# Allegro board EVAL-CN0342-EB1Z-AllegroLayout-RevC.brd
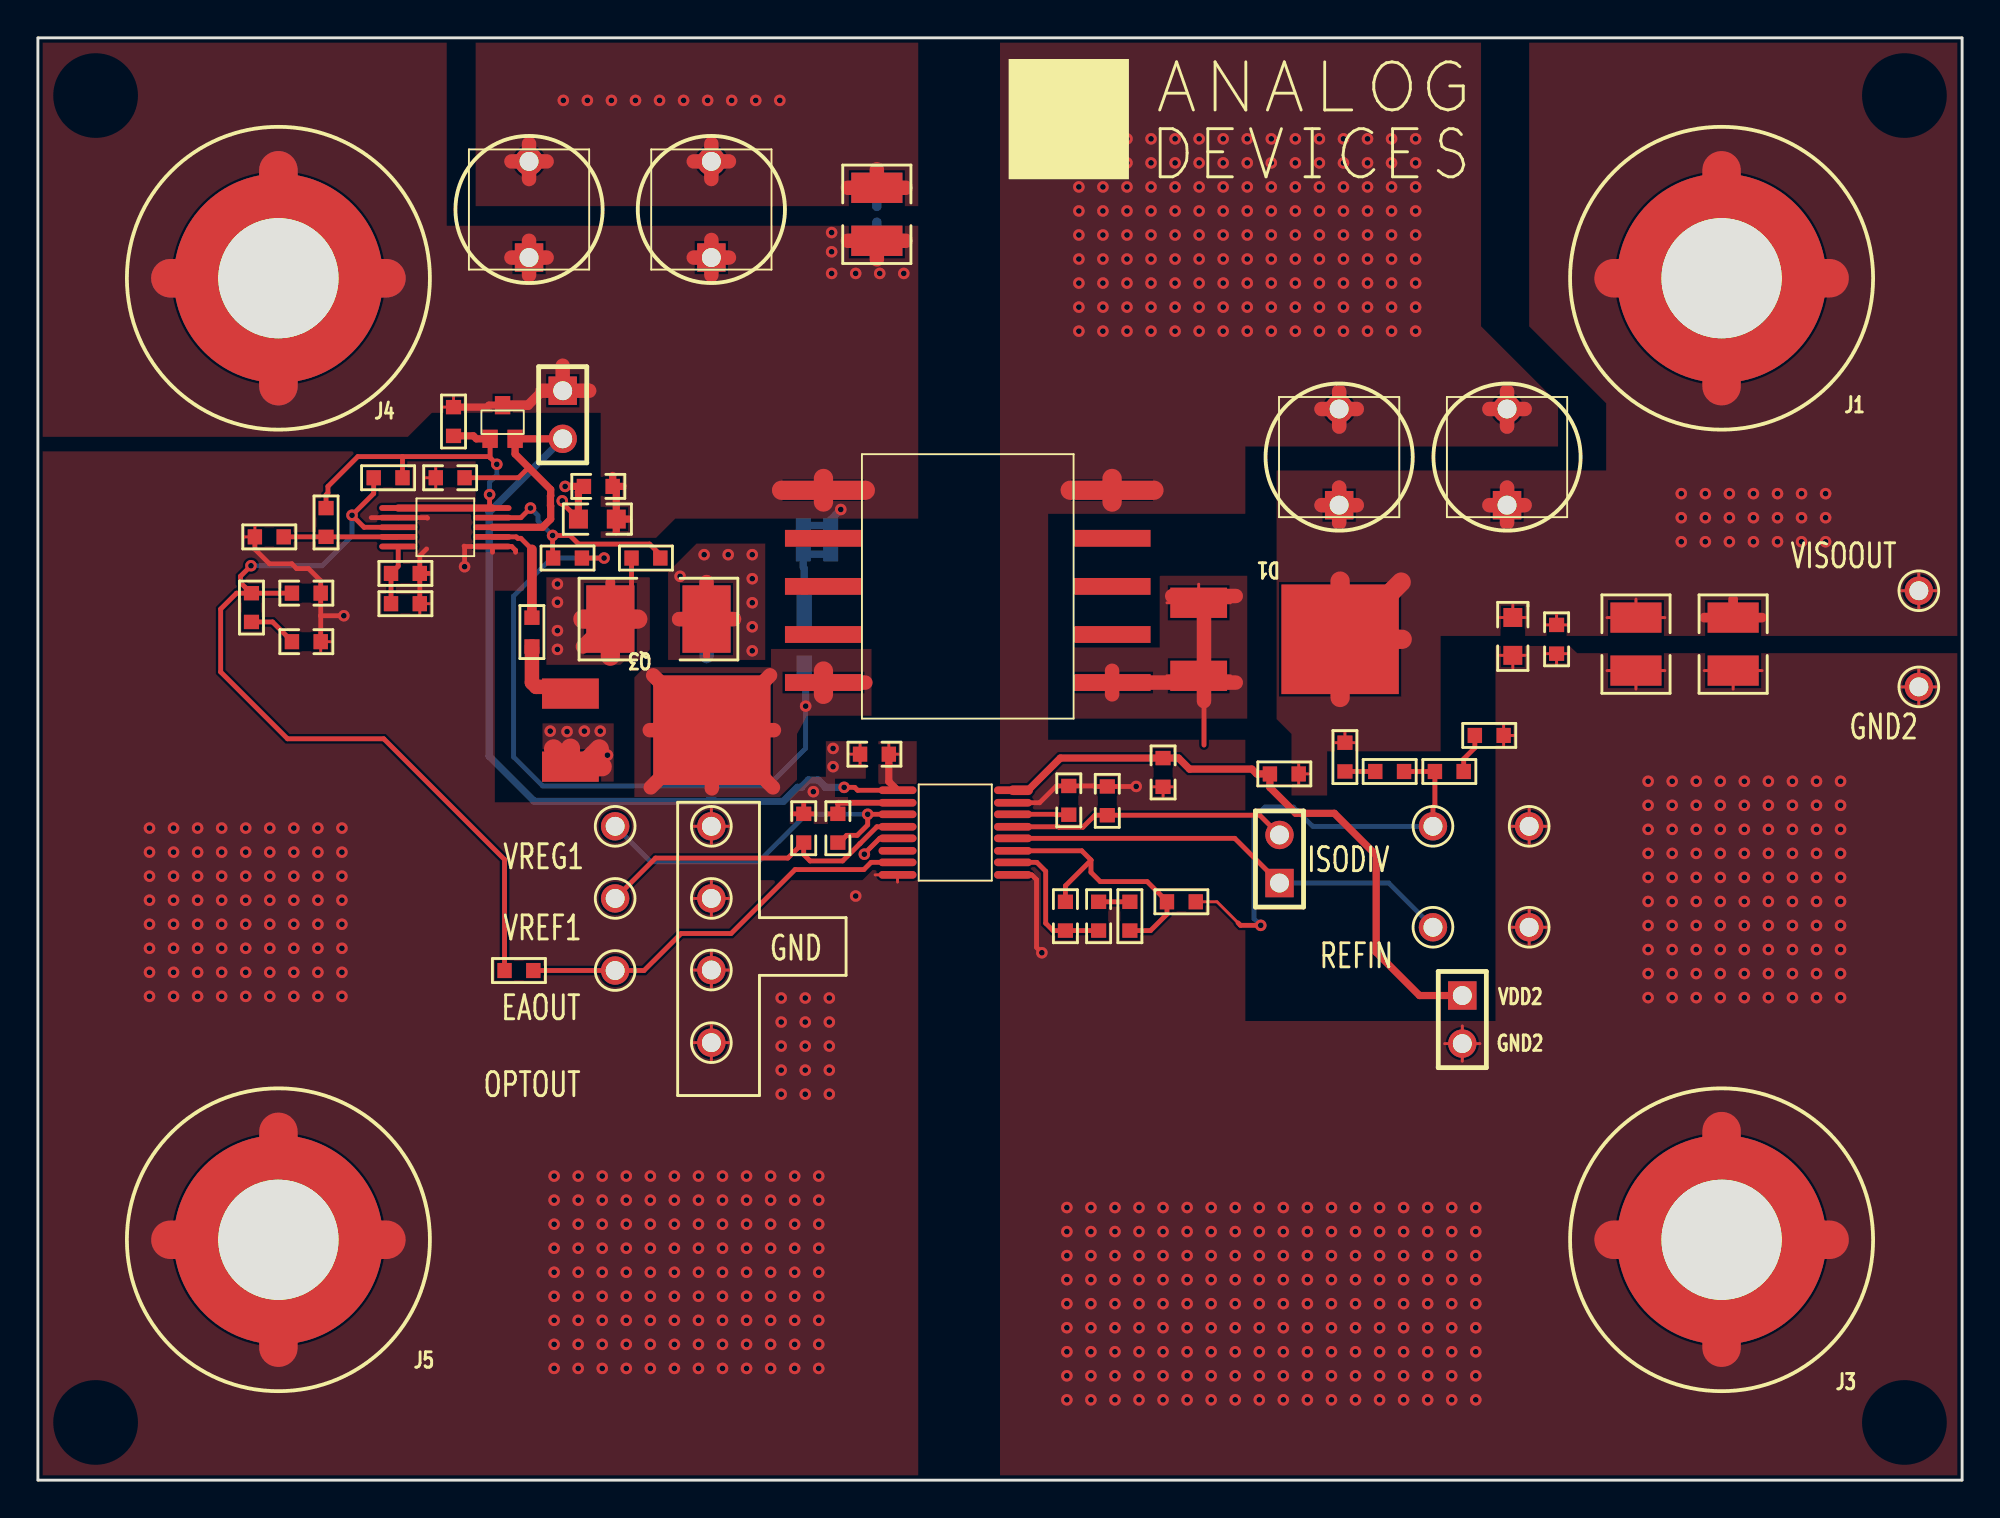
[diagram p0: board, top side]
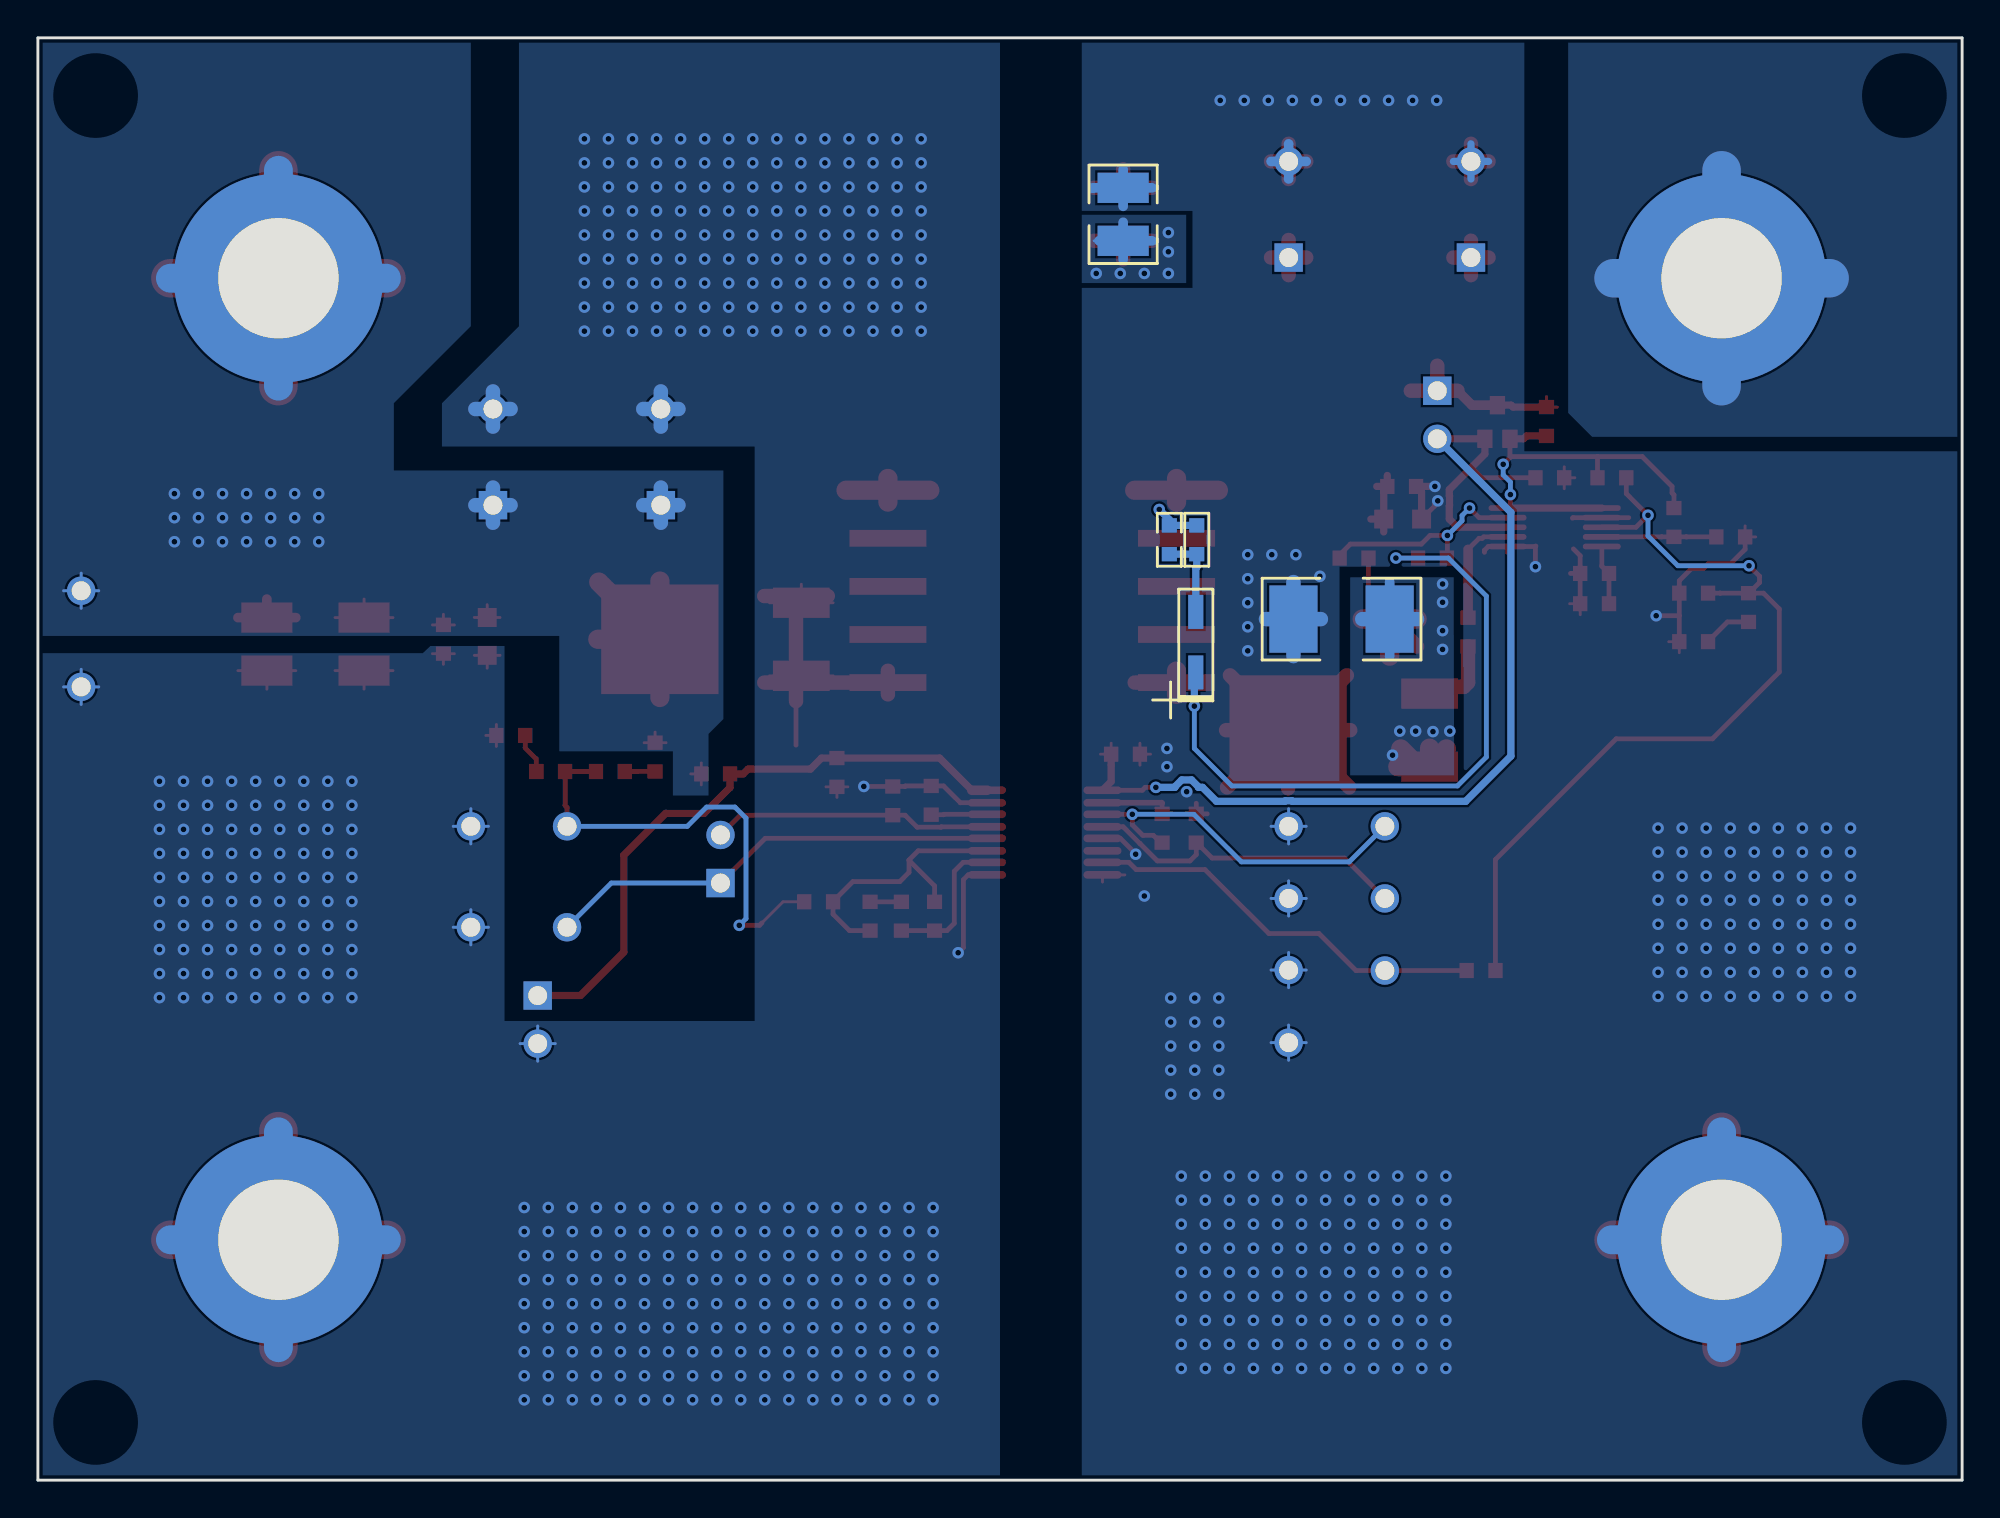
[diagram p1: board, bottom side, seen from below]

Outline 101.6 x 76.2 mm; copper layers: TOP, BOTTOM. Coordinates in mm from the lower left corner of the outline.
Outline path: 0,76.2 0,0 ; 0,76.2 0,0 ; 0,76.2 101.6,76.2 ; 0,76.2 101.6,76.2 ; 0,0 101.6,0 ; 0,0 101.6,0 ; 101.6,0 101.6,76.2 ; 101.6,0 101.6,76.2

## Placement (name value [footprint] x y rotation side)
C1  1uF  [C0603]  80.19 44.42 270 top
C2  10uF  [C0805]  77.88 44.58 270 top
C3  150uF  [CAX5]  68.71 54.05 90 top
C4  150uF  [CAX5]  77.57 54.05 90 top
C5  100nF  [C0603]  54.43 35.92 90 top
C6  100nF  [C0603]  42.24 34.44 90 top
C7  DP  [C0603]  14.17 44.3 0 top
C8  DP  [C0603]  14.17 46.86 0 top
C9  DP  [C0603]  56.01 29.79 90 top
C10  DP  [C0603]  54.25 29.79 90 top
C12  1uF  [C0603]  29.59 52.5 180 top
C13  10uF  [C0805]  29.54 50.77 180 top
C14  150uF  [CAX5]  35.56 67.13 90 top
C15  150uF  [CAX5]  25.93 67.13 90 top
C16  100nF  [C0603]  56.46 35.89 90 top
C17  1uF  [C0603]  44.17 38.35 180 top
C18  1uF  [C0603]  21.77 52.96 180 top
C19  100nF  [C0603]  40.44 34.44 90 top
C20  100nF  [C0603]  59.41 37.39 270 top
C21  DP  [C0603]  41.86 49.68 90 bottom
C23  47uF  [C1210]  84.38 44.17 270 top
C24  47uF  [C1210]  89.51 44.17 270 top
C25  47uF  [C1210]  44.3 66.88 90 top
C26  47uF  [C1210]  44.3 66.88 90 bottom
D1  MBRD1045G  [DPAK]  68.76 44.42 180 top
D2  MBR0540T1-D  [SOD-123]  40.46 44.27 90 bottom
J1  BANANA_JACK  [POWERJACK]  88.9 63.5 0 top
J3  BANANA_JACK  [POWERJACK]  88.9 12.7 0 top
J4  BANANA_JACK  [POWERJACK]  12.7 63.5 0 top
J5  BANANA_JACK  [POWERJACK]  12.7 12.7 0 top
J7  CON2x1  [HEADER2-100]  27.71 57.56 270 top
J14  CON2x1  [HEADER2-100]  75.21 25.6 270 top
J15  CON2x1  [HEADER2-100]  65.56 31.55 90 top
NOREF  -  [unnamed]  3.05 73.15 0 top
NOREF#2  -  [unnamed]  98.55 3.05 0 top
NOREF#3  -  [unnamed]  98.55 73.15 0 top
NOREF#4  -  [unnamed]  3.05 3.05 0 top
NOREF#5  -  [#2]  51.26 68.73 180 bottom
Q2  MMBT5089L  [SC70]  23.88 55.02 90 top
Q3  NTD18N06L  [DPAK]  35.59 39.62 180 top
R1  2k  [R0603]  76.63 39.34 0 top
R2  47k  [R0603]  74.52 37.44 0 top
R3  51k  [R0603]  71.37 37.44 0 top
R4  100k  [R0603]  69.01 38.2 270 top
R5  80  [R0603]  27.97 48.72 0 top
R6  100k  [R0603]  19.41 47.9 0 top
R7  DP  [R0603]  19.41 46.3 0 top
R8  DP  [R0603]  11.28 46.1 270 top
R9  DP  [R0603]  57.66 29.79 270 top
R11  0  [R0603]  60.38 30.56 0 top
R12  820  [R0603]  21.95 55.93 90 top
R13  100  [R0603]  65.81 37.31 180 top
R16  0  [R0603]  26.09 44.81 270 top
R17  DP  [R0603]  15.21 50.6 270 top
R18  0  [R0603]  12.22 49.83 0 top
R19  DP  [R0603]  40.41 49.68 90 bottom
R20  0  [R2010]  32.77 45.49 0 top
R21  0  [R2010]  32.77 45.49 0 bottom
R22  DP  [R0603]  32.11 48.72 180 top
R23  0  [R0603]  25.4 26.92 0 top
R24  0  [R0603]  18.49 52.96 0 top
TP1  TP-S  [HEADER1]  30.48 34.54 0 top
TP2  TP-S  [HEADER1]  30.48 30.73 0 top
TP3  TP-S  [HEADER1]  30.48 26.92 0 top
TP4  TP-S  [HEADER1]  73.66 29.21 0 top
TP6  TP-S  [HEADER1]  73.66 34.54 0 top
TP7  TP-S  [HEADER1]  35.56 34.54 0 top
TP8  TP-S  [HEADER1]  35.56 30.73 0 top
TP9  TP-S  [HEADER1]  35.56 26.95 0 top
TP10  TP-S  [HEADER1]  78.74 34.54 0 top
TP11  TP-S  [HEADER1]  78.74 29.21 0 top
TP13  TP-S  [HEADER1]  35.56 23.11 0 top
TP14  TP-S  [HEADER1]  99.31 41.91 0 top
TP15  TP-S  [HEADER1]  99.31 46.99 0 top
U2  ADuM3190  [QSOP-16]  48.44 34.21 0 top
U3  Halo 1 to 1 Flyback 2k5V iso  [TGB01]  49.1 47.22 0 top
U4  ADP1621  [MSOP-10]  21.51 50.34 0 top

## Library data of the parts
C1 C7-C10 C12 C17 C18 C21 = Cap_1U_0603_25V_X7R
C2 C13 = Cap_10U_0805_16V_X5R
C3 C4 C14 C15 = Cap_150U_RL2_0_6V_Alu
C5 C6 C16 C19 C20 = Cap_100n_0603_25V_X7R
C23-C26 = Cap_47U_1210_10V_X7R
D1 = MBRD1045G
D2 = MBR0540T1-D
J1 J3-J5 = BANANA_JACK
J7 J14 J15 = CON2x1
Q2 = MMBT5089L
Q3 = NTD18N06L
R1-R9 R11-R13 R16-R19 R22-R24 = Res_1k_0603_1%
R20 R21 = Res_0R5_2010_1%
TP1-TP4 TP6-TP11 TP13-TP15 = TP-S
U2 = ADuM3190
U3 = Halo 1 to 1 Flyback 2k5V iso
U4 = ADP1621

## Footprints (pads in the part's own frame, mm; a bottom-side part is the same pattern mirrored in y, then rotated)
C0603
  rect 0.76x0.8 smd: 1(-0.76,0) 2(0.76,0)
C0805
  rect 1x1 smd: 1(-1,0) 2(1,0)
C1210
  rect 1.6x2.7 smd: 1(-1.4,0) 2(1.4,0)
CAX5
  rect 1.5x1.5 hole 1: 1(-2.54,0)
  round 1.5 hole 1: 2(2.54,0)
DPAK
  rect 2.997x1.6 smd: 1(7.468,-1.93) 3(7.468,1.93)
  rect 6.198x5.791 smd: 4(0,0)
HEADER1
  round 1.5 hole 1: 1(0,0)
HEADER2-100
  rect 1.5x1.5 hole 1: 1(0,0)
  round 1.5 hole 1: 2(2.54,0)
MSOP-10
  oval 2.007x0.305 smd: 1(-2.489,1.016) 2(-2.489,0.508) 3(-2.489,0) 4(-2.489,-0.508) 5(-2.489,-1.016) 6(2.489,-1.016) 7(2.489,-0.508) 8(2.489,0) 9(2.489,0.508) 10(2.489,1.016)
POWERJACK
  round 11.05 hole 6.35: 1(0,0)
QSOP-16
  oval 2.007x0.406 smd: 1(-3.048,2.235) 2(-3.048,1.575) 3(-3.048,0.965) 4(-3.048,0.305) 5(-3.048,-0.305) 6(-3.048,-0.965) 7(-3.048,-1.575) 8(-3.048,-2.235) 9(3.048,-2.235) 10(3.048,-1.575) 11(3.048,-0.965) 12(3.048,-0.305) 13(3.048,0.305) 14(3.048,0.965) 15(3.048,1.575) 16(3.048,2.235)
R0603
  rect 0.76x0.8 smd: 1(-0.76,0) 2(0.76,0)
R2010
  rect 2.54x3.556 smd: 1(-2.54,0) 2(2.54,0)
SC70
  rect 0.965x0.813 smd: 1(0,0) 2(0,-1.321) 3(1.778,-0.66)
SOD-123
  rect 1.8x0.8 smd: 1(-1.6,0) 2(1.6,0)
TGB01
  rect 4.064x0.889 smd: 1(-7.62,5.08) 2(-7.62,2.54) 3(-7.62,0) 4(-7.62,-2.54) 5(-7.62,-5.08) 6(7.62,-5.08) 7(7.62,-2.54) 8(7.62,0) 9(7.62,2.54) 10(7.62,5.08)
unnamed
  round 0 hole 4.064 unplated: (0,0)

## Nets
GND1: C6.2 C7.2 C8.2 C12.2 C13.2 C14.2 C15.2 C17.2 C18.2 C19.2 C25.2 C26.2 J5.1(POWER IN) R6.2 R7.2 R18.1 R20.2 R21.2 TP7.1(VIA) TP8.1(VIA) TP9.1(VIA) TP13.1(VIA) U2.2(GND1_1) U2.5(NC_1) U2.8(GND1_2) U4.2(GND) U4.6(PGND)
GND2: C1.2 C2.2 C3.2 C4.2 C5.2 C16.2 C20.2 C23.2 C24.2 J3.1(POWER IN) J14.2 R1.2 TP10.1(VIA) TP11.1(VIA) TP14.1(VIA) U2.9(GND2_2) U2.15(GND2_1) U3.10
VDD1: C17.1 C18.1 J7.2 Q2.2(E) U2.1(VDD1) U4.8(PIN)
VDD_1621: Q2.1(B) R12.1 R17.1 R24.2 U4.1(SDSN) U4.10(IN)
VIN: C12.1 C13.1 C14.1 C15.1 C21.2 C25.1 C26.1 J4.1(POWER IN) J7.1 Q2.3(C) R12.2 R19.2 U3.1
COMP: C8.1 R8.1 R23.1 R24.1 U4.3(COMP)
EAOUT: R23.2 TP3.1(VIA) U2.7(EAOUT)
EAOUT2: U2.6(NC_2)
FB: R17.2 R18.2 U4.4(FB)
ISO_DIV: R2.1 R3.2 R11.2 TP6.1(VIA)
ISO_FB: C10.2 R9.2 R11.1 U2.11(FB)
ISO_REFIN: J15.1 TP4.1(VIA) U2.12(REFIN)
ISO_REFOUT: C16.1 J15.2 U2.13(REFOUT)
ISO_VDD2: C20.1 J14.1 R13.2 U2.16(VDD2)
ISO_VOUT: C1.1 C2.1 C3.1 C4.1 C23.1 C24.1 D1.4 J1.1(POWER IN) R4.1 R13.1 TP15.1(VIA)
ISO_VOUT_1: D1.1 D1.3 U3.6
REFOUT1: C19.1 TP2.1(VIA) U2.4(REFOUT1)
VREG1: C6.1 TP1.1(VIA) U2.3(VREG1)
N01085: R16.1 U4.7(GATE)
N02537: D2.1(ANODE) Q3.4(D) R5.2 U3.5
N02557: R5.1 R22.1 U4.9(CS)
N02646: R6.1 R7.1 U4.5(FREQ)
N03158: C7.1 R8.2
N03612: C9.1 C10.1 U2.10(COMP)
N11488: C9.2 R9.1
N11838: C5.1 U2.14(VREG2)
N15603: Q3.1(G) R16.2
N23766: Q3.3(S) R20.1 R21.1 R22.2
N36415: C21.1 D2.2(CATHODE) R19.1
N37525: R3.1 R4.2
N37627: R1.1 R2.2

Pads without a net: U3 2 3 4 7 8 9

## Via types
v1: diameter 0.61, hole 0.305, TOP to BOTTOM, 659 vias

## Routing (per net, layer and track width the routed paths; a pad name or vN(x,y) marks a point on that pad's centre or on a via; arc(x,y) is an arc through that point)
GND1: length 153.8
  TOP w0.152: 44.21,31.98 U2.8 45.39,31.6 ; 43.41,37.78 C17.2 ; C17.2 43.41,38.93 ; C17.2 42.85,38.35 ; TP7.1 35.56,35.47 ; TP7.1 34.63,34.54 ; TP7.1 36.49,34.54 ; TP7.1 35.56,33.62 ; 20.45,52.96 C18.2 ; C18.2 21.01,53.54 ; C18.2 21.01,52.38 ; 15.49,44.3 C7.2 14.93,43.72 ; TP9.1 35.56,27.88 ; TP9.1 34.63,26.95 ; TP9.1 36.49,26.95 ; TP9.1 35.56,26.02 ; 34.63,23.11 TP13.1 ; TP13.1 35.56,22.19 ; TP13.1 35.56,24.04 ; TP13.1 36.49,23.11 ; TP8.1 35.56,31.66 ; TP8.1 34.63,30.73 ; TP8.1 36.49,30.73 ; TP8.1 35.56,29.81 ; 11.46,50.41 R18.1 10.9,49.83 ; 20.72,46.3 R7.2 20.17,45.73
  TOP w0.254: U4.6 22.53,49.33 ; U4.6 24,49.02 ; U4.6 25.02,49.33 25.22,49.12 25.22,49.02 ; 22.53,49.33 v1(22.53,48.26) ; 22.53,49.33 22.5,49.35 ; 14.93,45.67 C7.2 ; 14.93,45.67 v1(16.15,45.67) ; 14.93,45.67 C8.2 14.93,47.52 14.29,48.16 13.67,48.16 13.41,48.41 12.23,48.41 11.46,49.18 R18.1 ; v1(43.64,33.07) 43.64,33.1 44.45,33.91 U2.5 ; R6.2 20.17,48.84 20.52,49.2 ; R6.2 R7.2 ; R6.2 20.68,47.9 ; C19.2 41.02,35.2 ; C19.2 39.86,35.2 ; C19.2 40.44,35.76 ; C13.2 27.86,51.45 27.86,51.57 v1(27.69,51.74) ; 17.6,50.85 U4.2 20.55,50.85 20.57,50.83 ; 41.66,35.2 C6.2 42.24,35.76
  TOP w0.305: U2.2 42.27,35.79 42.24,35.76
  TOP w0.381: v1(27.84,52.5) C12.2 28.54,52.21 C13.2 ; R20.2 35.31,43.54
  TOP w0.762: C25.2 45.83,68.28 ; C25.2 42.77,68.28 ; C25.2 44.3,69.26 ; R20.2 33.86,45.49 ; R20.2 36.75,45.49 ; R20.2 35.31,47.45 ; C14.2 35.56,70.6 ; C14.2 34.63,69.67 ; C14.2 35.56,68.74 ; C14.2 36.49,69.67 ; C15.2 25.93,68.74 ; C15.2 25.01,69.67 ; C15.2 25.93,70.6 ; C15.2 26.86,69.67
  TOP w2.032: J5.1 12.7,7 ; J5.1 18.4,12.7 ; J5.1 12.7,18.4 ; J5.1 7,12.7
  BOTTOM w0.152: 35.56,26.02 TP9.1 ; TP9.1 36.49,26.95 ; TP9.1 34.63,26.95 ; TP9.1 35.56,27.88 ; TP13.1 35.56,24.04 ; TP13.1 36.49,23.11 ; TP13.1 35.56,22.19 ; TP13.1 34.63,23.11 ; TP7.1 35.56,35.47 ; TP7.1 34.63,34.54 ; TP7.1 36.49,34.54 ; TP7.1 35.56,33.62 ; 34.63,30.73 TP8.1 ; TP8.1 36.49,30.73 ; TP8.1 35.56,29.81 ; TP8.1 35.56,31.66
  BOTTOM w0.381: C15.2 26.86,69.67 ; C15.2 25.93,68.74 ; C15.2 25.01,69.67 ; C15.2 25.93,70.6
  BOTTOM w0.508: C14.2 34.63,69.67 ; C14.2 35.56,68.74 ; C14.2 36.49,69.67 ; C14.2 35.56,70.6 ; 45.9,68.25 45.87,68.28 C25.2 ; C25.2 44.3,69.26 ; C25.2 42.77,68.28 ; C25.2 44.3,67.3
  BOTTOM w0.762: 36.75,45.49 R20.2 ; R20.2 35.31,47.45 ; R20.2 33.86,45.49 ; R20.2 35.31,43.54
  BOTTOM w1.524: J5.1 12.7,18.4 ; J5.1 18.52,12.7 ; J5.1 12.7,7 ; J5.1 7,12.7
  vias: v1(5.89,34.45) v1(5.89,33.18) v1(5.89,31.91) v1(5.89,30.64) v1(5.89,29.37) v1(5.89,28.1) v1(5.89,26.83) v1(5.89,25.56) v1(7.16,34.45) v1(7.16,33.18) v1(7.16,31.91) v1(7.16,30.64) v1(7.16,29.37) v1(7.16,28.1) v1(7.16,26.83) v1(7.16,25.56) v1(8.43,34.45) v1(8.43,33.18) v1(8.43,31.91) v1(8.43,30.64) v1(8.43,29.37) v1(8.43,28.1) v1(8.43,26.83) v1(8.43,25.56) v1(9.7,34.45) v1(9.7,33.18) v1(9.7,31.91) v1(9.7,30.64) v1(9.7,29.37) v1(9.7,28.1) v1(9.7,26.83) v1(9.7,25.56) v1(10.97,34.45) v1(10.97,33.18) v1(10.97,31.91) v1(10.97,30.64) v1(10.97,29.37) v1(10.97,28.1) v1(10.97,26.83) v1(10.97,25.56) v1(12.24,34.45) v1(12.24,33.18) v1(12.24,31.91) v1(12.24,30.64) v1(12.24,29.37) v1(12.24,28.1) v1(12.24,26.83) v1(12.24,25.56) v1(13.51,34.45) v1(13.51,33.18) v1(13.51,31.91) v1(13.51,30.64) v1(13.51,29.37) v1(13.51,28.1) v1(13.51,26.83) v1(13.51,25.56) v1(14.78,34.45) v1(14.78,33.18) v1(14.78,31.91) v1(14.78,30.64) v1(14.78,29.37) v1(14.78,28.1) v1(14.78,26.83) v1(14.78,25.56) v1(16.05,34.45) v1(16.05,33.18) v1(16.05,31.91) v1(16.05,30.64) v1(16.05,29.37) v1(16.05,28.1) v1(16.05,26.83) v1(16.05,25.56) v1(27.26,16.06) v1(27.26,14.79) v1(27.26,13.52) v1(27.26,12.25) v1(27.26,10.98) v1(27.26,9.71) v1(27.26,8.44) v1(27.26,7.17) v1(27.26,5.9) v1(27.74,72.9) v1(28.53,16.06) v1(28.53,14.79) v1(28.53,13.52) v1(28.53,12.25) v1(28.53,10.98) v1(28.53,9.71) v1(28.53,8.44) v1(28.53,7.17) v1(28.53,5.9) v1(29.01,72.9) v1(29.8,16.06) v1(29.8,14.79) v1(29.8,13.52) v1(29.8,12.25) v1(29.8,10.98) v1(29.8,9.71) v1(29.8,8.44) v1(29.8,7.17) v1(29.8,5.9) v1(30.28,72.9) v1(31.07,16.06) v1(31.07,14.79) v1(31.07,13.52) v1(31.07,12.25) v1(31.07,10.98) v1(31.07,9.71) v1(31.07,8.44) v1(31.07,7.17) v1(31.07,5.9) v1(31.55,72.9) v1(32.34,16.06) v1(32.34,14.79) v1(32.34,13.52) v1(32.34,12.25) v1(32.34,10.98) v1(32.34,9.71) v1(32.34,8.44) v1(32.34,7.17) v1(32.34,5.9) v1(32.82,72.9) v1(33.61,16.06) v1(33.61,14.79) v1(33.61,13.52) v1(33.61,12.25) v1(33.61,10.98) v1(33.61,9.71) v1(33.61,8.44) v1(33.61,7.17) v1(33.61,5.9) v1(33.91,47.75) v1(34.09,72.9) v1(34.88,16.06) v1(34.88,14.79) v1(34.88,13.52) v1(34.88,12.25) v1(34.88,10.98) v1(34.88,9.71) v1(34.88,8.44) v1(34.88,7.17) v1(34.88,5.9) v1(35.18,48.9) v1(35.36,72.9) v1(36.15,16.06) v1(36.15,14.79) v1(36.15,13.52) v1(36.15,12.25) v1(36.15,10.98) v1(36.15,9.71) v1(36.15,8.44) v1(36.15,7.17) v1(36.15,5.9) v1(36.45,48.9) v1(36.63,72.9) v1(37.42,16.06) v1(37.42,14.79) v1(37.42,13.52) v1(37.42,12.25) v1(37.42,10.98) v1(37.42,9.71) v1(37.42,8.44) v1(37.42,7.17) v1(37.42,5.9) v1(37.72,48.9) v1(37.72,47.62) v1(37.72,46.36) v1(37.72,45.09) v1(37.72,43.81) v1(37.9,72.9) v1(38.69,16.06) v1(38.69,14.79) v1(38.69,13.52) v1(38.69,12.25) v1(38.69,10.98) v1(38.69,9.71) v1(38.69,8.44) v1(38.69,7.17) v1(38.69,5.9) v1(39.17,72.9) v1(39.25,25.47) v1(39.25,24.2) v1(39.25,22.93) v1(39.25,21.66) v1(39.25,20.39) v1(39.96,16.06) v1(39.96,14.79) v1(39.96,13.52) v1(39.96,12.25) v1(39.96,10.98) v1(39.96,9.71) v1(39.96,8.44) v1(39.96,7.17) v1(39.96,5.9) v1(40.52,25.47) v1(40.52,24.2) v1(40.52,22.93) v1(40.52,21.66) v1(40.52,20.39) v1(40.94,36.37) v1(41.23,16.06) v1(41.23,14.79) v1(41.23,13.52) v1(41.23,12.25) v1(41.23,10.98) v1(41.23,9.71) v1(41.23,8.44) v1(41.23,7.17) v1(41.23,5.9) v1(41.79,25.47) v1(41.79,24.2) v1(41.79,22.93) v1(41.79,21.66) v1(41.79,20.39) v1(41.99,38.66) v1(41.99,37.69) v1(43.18,30.86)
GND2: length 123.4
  TOP w0.152: 74.28,23.06 J14.2 ; J14.2 75.21,22.13 ; J14.2 75.21,23.99 ; J14.2 76.14,23.06 ; 87.98,42.77 C24.2 ; C24.2 91.04,42.77 ; C24.2 89.51,41.79 ; 99.31,40.98 TP14.1 ; TP14.1 100.24,41.91 ; TP14.1 99.31,42.84 ; TP14.1 98.39,41.91 ; 77.81,34.54 TP10.1 ; TP10.1 78.74,33.62 ; TP10.1 78.74,35.47 ; TP10.1 79.67,34.54 ; 77.2,43.58 C2.2 ; C2.2 78.55,43.58 ; C2.2 77.88,42.9 ; TP11.1 79.67,29.21 ; TP11.1 78.74,28.28 ; TP11.1 77.81,29.21 ; TP11.1 78.74,30.14 ; 58.83,36.63 C20.2 ; C20.2 59.41,36.07 ; C20.2 59.99,36.63 ; 79.61,43.66 C1.2 ; C1.2 80.77,43.66 ; C1.2 80.19,43.11 ; C23.2 85.91,42.77 ; C23.2 82.85,42.77 ; C23.2 84.38,41.79 ; R1.2 77.39,39.92 ; R1.2 77.39,38.77 ; R1.2 77.95,39.34
  TOP w0.254: v1(53.01,27.86) 52.73,28.14 52.73,31.72 52.48,31.98 U2.9 ; v1(57.99,36.65) C16.2 55.81,36.65 55.78,36.68 C5.2 53.78,36.68 52.89,35.79 U2.15
  TOP w0.762: C3.2 67.78,56.59 ; C3.2 69.64,56.59 ; C3.2 68.71,57.52 ; C3.2 68.71,55.66 ; C4.2 76.64,56.59 ; C4.2 77.57,57.52 ; C4.2 77.57,55.66 ; C4.2 78.5,56.59
  TOP w1.016: U3.10 58.93,52.3 ; U3.10 56.72,51.68 ; U3.10 54.51,52.3 ; U3.10 56.72,52.92
  TOP w2.032: J3.1 94.6,12.7 ; J3.1 88.9,7 ; J3.1 83.2,12.7 ; J3.1 88.9,18.44
  BOTTOM w0.152: 75.21,22.13 J14.2 ; J14.2 74.28,23.06 ; J14.2 75.21,23.99 ; J14.2 76.14,23.06 ; 77.81,29.21 TP11.1 ; TP11.1 78.74,30.14 ; TP11.1 79.67,29.21 ; TP11.1 78.74,28.28 ; TP10.1 79.67,34.54 ; TP10.1 77.81,34.54 ; TP10.1 78.74,33.62 ; TP10.1 78.74,35.47 ; TP14.1 100.24,41.91 ; TP14.1 99.31,42.84 ; TP14.1 99.31,40.98 ; TP14.1 98.39,41.91
  BOTTOM w0.762: C3.2 69.64,56.59 ; C3.2 67.78,56.59 ; C3.2 68.71,55.66 ; C3.2 68.71,57.52 ; C4.2 78.5,56.59 ; C4.2 76.64,56.59 ; C4.2 77.57,57.52 ; C4.2 77.57,55.66
  BOTTOM w1.524: J3.1 88.9,7 ; J3.1 88.9,18.4 ; J3.1 94.6,12.7 ; J3.1 83.2,12.7
  vias: v1(54.33,14.4) v1(54.33,13.13) v1(54.33,11.86) v1(54.33,10.59) v1(54.33,9.32) v1(54.33,8.05) v1(54.33,6.78) v1(54.33,5.51) v1(54.33,4.24) v1(54.96,70.86) v1(54.96,69.59) v1(54.96,68.32) v1(54.96,67.05) v1(54.96,65.78) v1(54.96,64.51) v1(54.96,63.24) v1(54.96,61.97) v1(54.96,60.7) v1(55.6,14.4) v1(55.6,13.13) v1(55.6,11.86) v1(55.6,10.59) v1(55.6,9.32) v1(55.6,8.05) v1(55.6,6.78) v1(55.6,5.51) v1(55.6,4.24) v1(56.23,70.86) v1(56.23,69.59) v1(56.23,68.32) v1(56.23,67.05) v1(56.23,65.78) v1(56.23,64.51) v1(56.23,63.24) v1(56.23,61.97) v1(56.23,60.7) v1(56.87,14.4) v1(56.87,13.13) v1(56.87,11.86) v1(56.87,10.59) v1(56.87,9.32) v1(56.87,8.05) v1(56.87,6.78) v1(56.87,5.51) v1(56.87,4.24) v1(57.5,70.86) v1(57.5,69.59) v1(57.5,68.32) v1(57.5,67.05) v1(57.5,65.78) v1(57.5,64.51) v1(57.5,63.24) v1(57.5,61.97) v1(57.5,60.7) v1(58.14,14.4) v1(58.14,13.13) v1(58.14,11.86) v1(58.14,10.59) v1(58.14,9.32) v1(58.14,8.05) v1(58.14,6.78) v1(58.14,5.51) v1(58.14,4.24) v1(58.77,70.86) v1(58.77,69.59) v1(58.77,68.32) v1(58.77,67.05) v1(58.77,65.78) v1(58.77,64.51) v1(58.77,63.24) v1(58.77,61.97) v1(58.77,60.7) v1(59.41,14.4) v1(59.41,13.13) v1(59.41,11.86) v1(59.41,10.59) v1(59.41,9.32) v1(59.41,8.05) v1(59.41,6.78) v1(59.41,5.51) v1(59.41,4.24) v1(60.04,70.86) v1(60.04,69.59) v1(60.04,68.32) v1(60.04,67.05) v1(60.04,65.78) v1(60.04,64.51) v1(60.04,63.24) v1(60.04,61.97) v1(60.04,60.7) v1(60.68,14.4) v1(60.68,13.13) v1(60.68,11.86) v1(60.68,10.59) v1(60.68,9.32) v1(60.68,8.05) v1(60.68,6.78) v1(60.68,5.51) v1(60.68,4.24) v1(61.31,70.86) v1(61.31,69.59) v1(61.31,68.32) v1(61.31,67.05) v1(61.31,65.78) v1(61.31,64.51) v1(61.31,63.24) v1(61.31,61.97) v1(61.31,60.7) v1(61.95,14.4) v1(61.95,13.13) v1(61.95,11.86) v1(61.95,10.59) v1(61.95,9.32) v1(61.95,8.05) v1(61.95,6.78) v1(61.95,5.51) v1(61.95,4.24) v1(62.58,70.86) v1(62.58,69.59) v1(62.58,68.32) v1(62.58,67.05) v1(62.58,65.78) v1(62.58,64.51) v1(62.58,63.24) v1(62.58,61.97) v1(62.58,60.7) v1(63.22,14.4) v1(63.22,13.13) v1(63.22,11.86) v1(63.22,10.59) v1(63.22,9.32) v1(63.22,8.05) v1(63.22,6.78) v1(63.22,5.51) v1(63.22,4.24) v1(63.85,70.86) v1(63.85,69.59) v1(63.85,68.32) v1(63.85,67.05) v1(63.85,65.78) v1(63.85,64.51) v1(63.85,63.24) v1(63.85,61.97) v1(63.85,60.7) v1(64.49,14.4) v1(64.49,13.13) v1(64.49,11.86) v1(64.49,10.59) v1(64.49,9.32) v1(64.49,8.05) v1(64.49,6.78) v1(64.49,5.51) v1(64.49,4.24) v1(65.12,70.86) v1(65.12,69.59) v1(65.12,68.32) v1(65.12,67.05) v1(65.12,65.78) v1(65.12,64.51) v1(65.12,63.24) v1(65.12,61.97) v1(65.12,60.7) v1(65.76,14.4) v1(65.76,13.13) v1(65.76,11.86) v1(65.76,10.59) v1(65.76,9.32) v1(65.76,8.05) v1(65.76,6.78) v1(65.76,5.51) v1(65.76,4.24) v1(66.39,70.86) v1(66.39,69.59) v1(66.39,68.32) v1(66.39,67.05) v1(66.39,65.78) v1(66.39,64.51) v1(66.39,63.24) v1(66.39,61.97) v1(66.39,60.7) v1(67.03,14.4) v1(67.03,13.13) v1(67.03,11.86) v1(67.03,10.59) v1(67.03,9.32) v1(67.03,8.05) v1(67.03,6.78) v1(67.03,5.51) v1(67.03,4.24) v1(67.66,70.86) v1(67.66,69.59) v1(67.66,68.32) v1(67.66,67.05) v1(67.66,65.78) v1(67.66,64.51) v1(67.66,63.24) v1(67.66,61.97) v1(67.66,60.7) v1(68.3,14.4) v1(68.3,13.13) v1(68.3,11.86) v1(68.3,10.59) v1(68.3,9.32) v1(68.3,8.05) v1(68.3,6.78) v1(68.3,5.51) v1(68.3,4.24) v1(68.93,70.86) v1(68.93,69.59) v1(68.93,68.32) v1(68.93,67.05) v1(68.93,65.78) v1(68.93,64.51) v1(68.93,63.24) v1(68.93,61.97) v1(68.93,60.7) v1(69.57,14.4) v1(69.57,13.13) v1(69.57,11.86) v1(69.57,10.59) v1(69.57,9.32) v1(69.57,8.05) v1(69.57,6.78) v1(69.57,5.51) v1(69.57,4.24) v1(70.2,70.86) v1(70.2,69.59) v1(70.2,68.32) v1(70.2,67.05) v1(70.2,65.78) v1(70.2,64.51) v1(70.2,63.24) v1(70.2,61.97) v1(70.2,60.7) v1(70.84,14.4) v1(70.84,13.13) v1(70.84,11.86) v1(70.84,10.59) v1(70.84,9.32) v1(70.84,8.05) v1(70.84,6.78) v1(70.84,5.51) v1(70.84,4.24) v1(71.47,70.86) v1(71.47,69.59) v1(71.47,68.32) v1(71.47,67.05) v1(71.47,65.78) v1(71.47,64.51) v1(71.47,63.24) v1(71.47,61.97) v1(71.47,60.7) v1(72.11,14.4) v1(72.11,13.13) v1(72.11,11.86) v1(72.11,10.59) v1(72.11,9.32) v1(72.11,8.05) v1(72.11,6.78) v1(72.11,5.51) v1(72.11,4.24) v1(72.74,70.86) v1(72.74,69.59) v1(72.74,68.32) v1(72.74,67.05) v1(72.74,65.78) v1(72.74,64.51) v1(72.74,63.24) v1(72.74,61.97) v1(72.74,60.7) v1(73.38,14.4) v1(73.38,13.13) v1(73.38,11.86) v1(73.38,10.59) v1(73.38,9.32) v1(73.38,8.05) v1(73.38,6.78) v1(73.38,5.51) v1(73.38,4.24) v1(74.65,14.4) v1(74.65,13.13) v1(74.65,11.86) v1(74.65,10.59) v1(74.65,9.32) v1(74.65,8.05) v1(74.65,6.78) v1(74.65,5.51) v1(74.65,4.24) v1(75.92,14.4) v1(75.92,13.13) v1(75.92,11.86) v1(75.92,10.59) v1(75.92,9.32) v1(75.92,8.05) v1(75.92,6.78) v1(75.92,5.51) v1(75.92,4.24) v1(85.02,36.92) v1(85.02,35.65) v1(85.02,34.38) v1(85.02,33.11) v1(85.02,31.84) v1(85.02,30.57) v1(85.02,29.3) v1(85.02,28.03) v1(85.02,26.76) v1(85.02,25.49) v1(86.29,36.92) v1(86.29,35.65) v1(86.29,34.38) v1(86.29,33.11) v1(86.29,31.84) v1(86.29,30.57) v1(86.29,29.3) v1(86.29,28.03) v1(86.29,26.76) v1(86.29,25.49) v1(87.56,36.92) v1(87.56,35.65) v1(87.56,34.38) v1(87.56,33.11) v1(87.56,31.84) v1(87.56,30.57) v1(87.56,29.3) v1(87.56,28.03) v1(87.56,26.76) v1(87.56,25.49) v1(88.83,36.92) v1(88.83,35.65) v1(88.83,34.38) v1(88.83,33.11) v1(88.83,31.84) v1(88.83,30.57) v1(88.83,29.3) v1(88.83,28.03) v1(88.83,26.76) v1(88.83,25.49) v1(90.1,36.92) v1(90.1,35.65) v1(90.1,34.38) v1(90.1,33.11) v1(90.1,31.84) v1(90.1,30.57) v1(90.1,29.3) v1(90.1,28.03) v1(90.1,26.76) v1(90.1,25.49) v1(91.37,36.92) v1(91.37,35.65) v1(91.37,34.38) v1(91.37,33.11) v1(91.37,31.84) v1(91.37,30.57) v1(91.37,29.3) v1(91.37,28.03) v1(91.37,26.76) v1(91.37,25.49) v1(92.64,36.92) v1(92.64,35.65) v1(92.64,34.38) v1(92.64,33.11) v1(92.64,31.84) v1(92.64,30.57) v1(92.64,29.3) v1(92.64,28.03) v1(92.64,26.76) v1(92.64,25.49) v1(93.91,36.92) v1(93.91,35.65) v1(93.91,34.38) v1(93.91,33.11) v1(93.91,31.84) v1(93.91,30.57) v1(93.91,29.3) v1(93.91,28.03) v1(93.91,26.76) v1(93.91,25.49) v1(95.18,36.92) v1(95.18,35.65) v1(95.18,34.38) v1(95.18,33.11) v1(95.18,31.84) v1(95.18,30.57) v1(95.18,29.3) v1(95.18,28.03) v1(95.18,26.76) v1(95.18,25.49)
VDD1: length 59.3
  TOP w0.152: 45.49,38.35 C17.1 44.93,38.93
  TOP w0.254: C18.1 25.37,52.96 25.91,53.5 ; v1(42.57,36.6) 43.13,36.6 43.28,36.45 U2.1
  TOP w0.381: C17.1 44.93,36.91 U2.1 ; J7.2 Q2.2 25.2,54.22 27.08,52.34 27.08,52.01 27.06,52 27.06,51.48 27.08,51.47 27.08,50.77 26.64,50.34 U4.8
  BOTTOM w0.381: J7.2 23.83,51.13 23.83,38.25 26.21,35.86 35.36,35.86 35.39,35.89 35.73,35.89 35.76,35.86 39.37,35.86 40.11,36.6 40.32,36.6 40.32,36.63 40.69,37 41.2,37 41.57,36.63 41.57,36.6 v1(42.57,36.6)
VDD_1621: length 22.5
  TOP w0.254: 19.25,54.08 16.89,54.08 15.32,52.5 15.32,52.16 15.21,52.06 R17.1 ; 19.25,54.08 19.25,54.07 R24.2 ; 19.25,54.08 23.83,54.08 23.88,54.03 ; 23.88,54.03 Q2.1 ; 23.88,54.03 v1(24.23,53.67) ; v1(23.85,52.07) 23.85,51.51 U4.10
  TOP w0.381: R12.1 23,55.17 23.15,55.02 Q2.1 ; U4.1 U4.10
  BOTTOM w0.254: v1(23.85,52.07) 23.85,52.73 24.23,53.11 v1(24.23,53.67)
VIN: length 84.5
  TOP w0.152: 21.37,56.69 R12.2 21.95,57.25
  TOP w0.381: C12.1 30.35,53.08 ; C12.1 30.54,52.31 C13.1 ; C12.1 30.91,52.5 ; R12.2 23.71,56.69 23.81,56.79 Q2.3 ; C13.1 30.54,50.1 ; C13.1 31.22,50.77
  TOP w0.508: 26.64,57.56 25.88,56.79 Q2.3
  TOP w0.762: C25.1 42.77,65.48 ; C25.1 45.83,65.48 ; C25.1 44.3,64.5 ; C14.1 35.56,63.66 ; C14.1 35.56,65.52 ; C14.1 36.49,64.59 ; C14.1 34.63,64.59 ; J7.1 26.64,57.56 ; J7.1 27.71,58.88 ; J7.1 29.11,57.56 ; C15.1 25.01,64.59 ; C15.1 26.86,64.59 ; C15.1 25.93,63.66 ; C15.1 25.93,65.48
  TOP w1.016: U3.1 41.48,51.68 ; U3.1 43.69,52.3 ; U3.1 41.48,52.92 ; U3.1 39.27,52.3
  TOP w2.032: J4.1 18.4,63.5 ; J4.1 12.7,57.8 ; J4.1 7,63.5 ; J4.1 12.7,69.2
  BOTTOM w0.152: 45.57,65.48 45.83,65.48
  BOTTOM w0.381: v1(42.39,51.28) 41.86,50.75 C21.2 R19.2
  BOTTOM w0.508: C25.1 44.3,64.5 ; C25.1 45.57,65.48 ; C25.1 42.77,65.48 ; C25.1 44.3,66.46
  BOTTOM w2.032: J4.1 12.7,69.2 ; J4.1 7,63.5 ; J4.1 12.7,57.8 ; J4.1 18.4,63.5
  vias: v1(41.91,65.91) v1(41.91,64.9) v1(41.91,63.75) v1(43.18,63.75) v1(44.45,63.75) v1(45.72,63.75)
COMP: length 46.5
  TOP w0.254: 11.26,46.86 10.7,47.42 10.7,47.76 v1(11.25,48.31) ; 11.26,46.86 10.49,46.86 9.65,46.02 9.65,42.7 13.18,39.17 18.26,39.17 24.64,32.79 R23.1 ; 11.26,46.86 R8.1 12.78,46.86 12.78,46.86 C8.1 ; U4.3 17.22,50.34 v1(16.59,50.98) 17.73,52.12 R24.1
  BOTTOM w0.254: v1(16.59,50.98) 16.59,49.89 15.01,48.31 v1(11.25,48.31)
EAOUT: length 21.6
  TOP w0.254: U2.7 43.99,32.64 43.61,32.26 39.98,32.26 36.6,28.88 33.96,28.88 32,26.92 TP3.1 R23.2
FB: length 6
  TOP w0.254: R18.2 14.56,49.83 14.56,49.84 R17.2 15.87,49.84 15.87,49.83 U4.4
ISO_DIV: length 24.4
  TOP w0.152: R11.2 62.26,30.56 63.37,29.44
  TOP w0.254: 63.37,29.44 63.5,29.31 v1(64.57,29.31) ; TP6.1 73.66,35.55 73.76,35.65 R2.1 R3.2
  BOTTOM w0.254: v1(64.57,29.31) 64.21,29.67 64.21,34.98 64.8,35.56 66.29,35.56 67.31,34.54 TP6.1
ISO_FB: length 15.4
  TOP w0.254: 55.6,32.75 55.6,32.77 55.12,33.25 U2.11 ; 55.6,32.75 55.6,32.11 56.09,31.62 58.57,31.62 59.62,30.58 R11.1 59.62,29.9 58.75,29.03 R9.2 ; 55.6,32.75 54.25,31.4 C10.2
ISO_REFIN: length 24.1
  TOP w0.254: U2.12 63.2,33.91 J15.1
  BOTTOM w0.254: J15.1 71.32,31.55 TP4.1
ISO_REFOUT: length 14.8
  TOP w0.254: U2.13 53.89,34.52 53.92,34.5 55.18,34.5 55.81,35.13 C16.1 64.51,35.13 J15.2
ISO_VDD2: length 33.1
  TOP w0.381: J14.1 72.95,25.6 70.66,27.89 70.66,33.02 68.45,35.23 66.42,35.23 65.05,36.6 R13.2 64.35,37.31 64.1,37.57 60.81,37.57 60.23,38.15 C20.1 53.99,38.15 52.29,36.45
  TOP w0.508: 52.29,36.45 U2.16
ISO_VOUT: length 96.9
  TOP w0.152: R13.1 66.57,37.89 ; R13.1 67.13,37.31 ; R13.1 66.57,36.73 ; C1.1 80.77,45.18 ; C1.1 80.19,45.74 ; C1.1 79.61,45.18 ; R4.1 69.01,39.52 ; R4.1 69.59,38.96 ; R4.1 68.43,38.96 ; TP15.1 99.31,47.92 ; TP15.1 100.24,46.99 ; TP15.1 98.39,46.99 ; TP15.1 99.31,46.06 ; C23.1 84.38,46.55 ; C23.1 85.91,45.57 ; C23.1 82.85,45.57 ; C2.1 78.55,45.58 ; C2.1 77.88,46.26 ; C2.1 77.2,45.58
  TOP w0.508: C24.1 91.04,45.57 ; C24.1 87.98,45.57 ; C24.1 89.51,46.55
  TOP w0.762: C3.1 67.78,51.51 ; C3.1 69.64,51.51 ; C3.1 68.71,52.44 ; C3.1 68.71,50.58 ; C4.1 76.64,51.51 ; C4.1 77.57,50.58 ; C4.1 78.5,51.51 ; C4.1 77.57,52.44
  TOP w1.016: 68.96,44.42 D1.4 ; 68.96,44.42 72.03,44.42 ; 68.96,44.42 71.98,47.45 ; D1.4 68.76,47.5 ; D1.4 68.76,41.35
  TOP w2.032: J1.1 88.9,57.8 ; J1.1 83.2,63.5 ; J1.1 94.6,63.5 ; J1.1 88.9,69.2
  BOTTOM w0.152: 99.31,46.06 TP15.1 ; TP15.1 100.24,46.99 ; TP15.1 98.39,46.99 ; TP15.1 99.31,47.92
  BOTTOM w0.762: C3.1 69.64,51.51 ; C3.1 67.78,51.51 ; C3.1 68.71,50.58 ; C3.1 68.71,52.44 ; C4.1 77.57,50.58 ; C4.1 76.64,51.51 ; C4.1 77.57,52.44 ; C4.1 78.5,51.51
  BOTTOM w1.524: J1.1 94.6,63.5 ; J1.1 88.9,57.8 ; J1.1 83.2,63.5 ; J1.1 88.9,69.2
  vias: v1(86.77,52.12) v1(86.77,50.85) v1(86.77,49.58) v1(88.04,52.12) v1(88.04,50.85) v1(88.04,49.58) v1(89.31,52.12) v1(89.31,50.85) v1(89.31,49.58) v1(90.58,52.12) v1(90.58,50.85) v1(90.58,49.58) v1(91.85,52.12) v1(91.85,50.85) v1(91.85,49.58) v1(93.12,52.12) v1(93.12,50.85) v1(93.12,49.58) v1(94.39,52.12) v1(94.39,50.85) v1(94.39,49.58)
ISO_VOUT_1: length 29.6
  TOP w0.152: D1.1 62.97,46.36 ; D1.1 61.29,47.33 ; D1.1 59.61,46.36 ; D1.1 61.29,45.38 ; D1.3 62.97,42.49 ; D1.3 59.61,42.49 ; D1.3 61.29,41.52 ; D1.3 61.29,43.47
  TOP w0.254: 61.57,41.16 61.57,41.16 61.57,38.84
  TOP w0.762: 61.57,42.14 U3.6 ; 61.57,42.14 61.57,41.16 ; 61.57,42.14 63.25,42.14 ; 61.57,42.14 61.57,46.71 ; U3.6 56.72,42.76 ; U3.6 56.72,41.52 ; 63.25,46.71 61.57,46.71 ; 61.57,46.71 59.89,46.71
REFOUT1: length 17.7
  TOP w0.254: U2.4 44.3,34.52 43.41,33.63 43.41,33.63 42.49,32.72 40.77,32.72 40.44,33.05 C19.1 40.42,33.68 39.6,32.87 32.61,32.87 TP2.1
VREG1: length 19.3
  TOP w0.254: 45.39,35.18 v1(43.81,35.18) 43.81,34.62 43.26,34.07 42.7,34.07 42.32,33.68 C6.1
  BOTTOM w0.254: TP1.1 32.36,32.66 38.05,32.66 40.56,35.18 v1(43.81,35.18)
N01085: length 6
  TOP w0.254: 26.09,49.17 25.5,49.76 25.34,49.76 25.26,49.83 U4.7
  TOP w0.508: R16.1 26.09,49.17
N02537: length 66
  TOP w0.254: R5.2 v1(29.9,48.72)
  TOP w0.762: 38.86,39.62 35.79,39.62 ; 35.79,39.62 38.81,36.6 ; 35.79,39.62 35.76,39.62 ; 35.38,39.62 32.31,39.62 ; 35.38,39.62 Q3.4 ; 35.38,39.62 32.49,42.52 ; 35.38,39.62 32.36,36.6 ; 35.76,39.62 Q3.4 ; 35.76,39.62 38.66,42.52 ; Q3.4 35.59,36.55 ; U3.5 43.69,42.14
  TOP w1.016: 41.48,42.75 U3.5 41.48,41.52
  BOTTOM w0.254: v1(29.9,48.72) 27.13,48.72 25.12,46.71 25.12,38.2 26.64,36.68 38.56,36.68 40.54,38.66 v1(40.54,40.89)
  BOTTOM w0.381: v1(40.54,40.89) 40.54,42.6 D2.1
N02557: length 11.6
  TOP w0.254: R22.1 32.87,48.89 32.3,49.45 28.55,49.45 28.09,49.91 v1(27.18,49.91) 27.18,48.74 R5.1 ; U4.9 25.5,50.85 v1(26.01,51.36)
  BOTTOM w0.254: v1(26.01,51.36) 26.4,50.96 26.4,50.68 v1(27.18,49.91)
N02646: length 3.2
  TOP w0.254: U4.5 19.02,48.28 R6.1 R7.1
N03158: length 2.6
  TOP w0.254: C7.1 13.41,44.32 12.39,45.34 R8.2
N03612: length 7.6
  TOP w0.254: U2.10 52.74,32.64 53.21,32.17 53.21,29.42 53.6,29.03 C10.1 C9.1
N11488: length 1.7
  TOP w0.254: C9.2 R9.1
N11838: length 3
  TOP w0.254: C5.1 53.78,35.16 53.75,35.18 51.49,35.18
N15603: length 4.2
  TOP w0.762: Q3.1 27.76,41.91 26.31,41.91 26.09,42.14 R16.2
N23766: length 24.6
  TOP w0.254: R20.1 31.35,46.61 R22.2
  TOP w0.508: R20.1 30.23,47.45
  TOP w0.762: 28.78,44.04 R20.1
  TOP w1.016: R20.1 31.67,45.49 ; R20.1 28.78,45.49 ; R20.1 30.23,43.54 ; 28.7,37.69 29.64,38.63 ; 28.7,37.69 29.79,37.69 ; 28.7,37.69 Q3.3 28.12,37.74 ; 28.12,37.74 28.12,38.67 ; 28.12,37.74 27.23,38.63
  BOTTOM w0.508: 30.23,43.54 R20.1 30.23,47.45
  BOTTOM w0.762: 31.67,45.49 R20.1 28.78,45.49
  vias: v1(27.05,39.57) v1(27.43,47.35) v1(27.43,46.38) v1(27.43,44.88) v1(27.43,43.89) v1(27.94,39.55) v1(28.85,39.57) v1(29.69,39.57) v1(30.07,38.3)
N36415: length 4.5
  BOTTOM w0.381: C21.1 R19.1 40.41,48.22 40.46,48.17 D2.2
N37525: length 1.6
  TOP w0.254: R4.2 69.98,37.44 69.98,37.44 R3.1
N37627: length 2.1
  TOP w0.254: R1.1 75.87,38.69 75.28,38.1 R2.2

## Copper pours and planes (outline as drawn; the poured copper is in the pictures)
GND1 on TOP: 42.77,34.67 42.77,36.09 42.09,36.09 42.09,37.06 43.71,37.06 43.71,39.04 41.61,39.04 41.61,37.16 40.89,37.16 39.7,35.97 39.7,34.67
GND1 on TOP: 33.27,47.98 33.27,43.33 38.4,43.33 38.4,49.48 34.77,49.48
GND1 on TOP: 23.11,75.95 23.11,67.31 46.48,67.31 46.48,75.95
GND1 on TOP: 0.25,54.36 0.25,0.25 46.48,0.25 46.48,32.13 46.38,32.23 44.07,32.23 43.54,31.7 38.1,31.7 38.1,35.81 24.13,35.81 24.13,46.99 25.65,46.99 25.65,49.02 23.11,49.02 23.11,54.36 ; 1 cut-out
GND1 on TOP: 20.29,50.95 20.29,49.12 22.73,49.12 22.73,50.95
GND1 on BOTTOM: 0.25,0.25 0.25,54.36 0.28,54.38 0.3,54.36 23.11,54.36 23.11,75.95 46.48,75.95 46.48,67.06 40.64,67.06 40.64,62.99 46.48,62.99 46.48,0.25 ; 1 cut-out
GND2 on TOP: 50.8,0.25 50.8,75.95 76.2,75.95 76.2,60.96 80.26,56.9 80.26,54.61 63.75,54.61 63.75,51.05 53.34,51.05 53.34,39.12 63.75,39.12 63.75,24.26 76.96,24.26 76.96,44.07 80.87,44.07 81.28,43.69 101.35,43.69 101.35,0.25 ; 4 cut-outs
GND2 on BOTTOM: 50.8,75.95 50.8,0.25 101.35,0.25 101.35,43.69 81.28,43.69 80.87,44.07 76.96,44.07 76.96,24.26 63.75,24.26 63.75,54.61 80.26,54.61 80.26,56.9 76.2,60.96 76.2,75.95
VDD1 on TOP: 44.37,36.22 46.41,36.22 46.41,39.04 44.37,39.04
VIN on TOP: 46.48,50.8 46.48,66.27 21.59,66.27 21.59,75.95 0.25,75.95 0.25,55.12 19.53,55.12 20.8,56.39 29.72,56.39 29.72,49.78 32.64,49.78 33.66,50.8
VIN on BOTTOM: 40.97,66.85 40.97,63.25 46.48,63.25 46.48,66.85
VIN on BOTTOM: 0.25,75.95 20.8,75.95 20.8,56.39 19.53,55.12 0.25,55.12
ISO_VOUT on TOP: 65.41,53.34 65.41,40.21 66.19,39.42 66.19,36.17 68.07,36.17 68.07,38.51 74.07,38.51 74.07,44.6 101.35,44.6 101.35,75.95 78.74,75.95 78.74,60.96 82.8,56.9 82.8,53.34
ISO_VOUT on BOTTOM: 66.19,36.17 68.07,36.17 68.07,38.51 74.07,38.51 74.07,44.6 101.35,44.6 101.35,75.95 78.74,75.95 78.74,60.96 82.8,56.9 82.8,53.34 65.41,53.34 65.41,40.21 66.19,39.42
ISO_VOUT_1 on TOP: 54.69,43.99 54.69,40.23 63.86,40.23 63.86,47.78 59.26,47.78 59.23,47.75 59.23,43.99
N02537 on TOP: 31.5,42.42 31.5,36.09 39.17,36.09 40.08,37.01 40.08,39.42 40.61,40.39 44.02,40.39 44.02,43.92 38.71,43.92 38.71,42.95 32.03,42.95
N23766 on TOP: 26.85,43.08 30.76,43.08 31.01,43.33 31.78,43.33 32.31,43.87 32.31,47.68 32.28,47.7 26.85,47.7
N23766 on TOP: 26.64,39.98 26.64,36.91 30.4,36.91 30.4,39.98
N23766 on BOTTOM: 32.31,37.24 32.31,47.7 26.85,47.7 26.82,37.24

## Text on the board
Ref Des/Silkscreen Top: GND2 | VDD2 | OPTOUT | EAOUT | VREG1 | VREF1 | GND | ISODIV | REFIN | VISOOUT
DISPLAY_TOP: FIGURE | SIZE | 12.0 | 39.37 | 250.0 | PLATED | FINISHED HOLES IN MILS | ALL UNITS ARE IN MILS | QTY | 161 | 31 | 4 | TOLERANCE/NOTES
